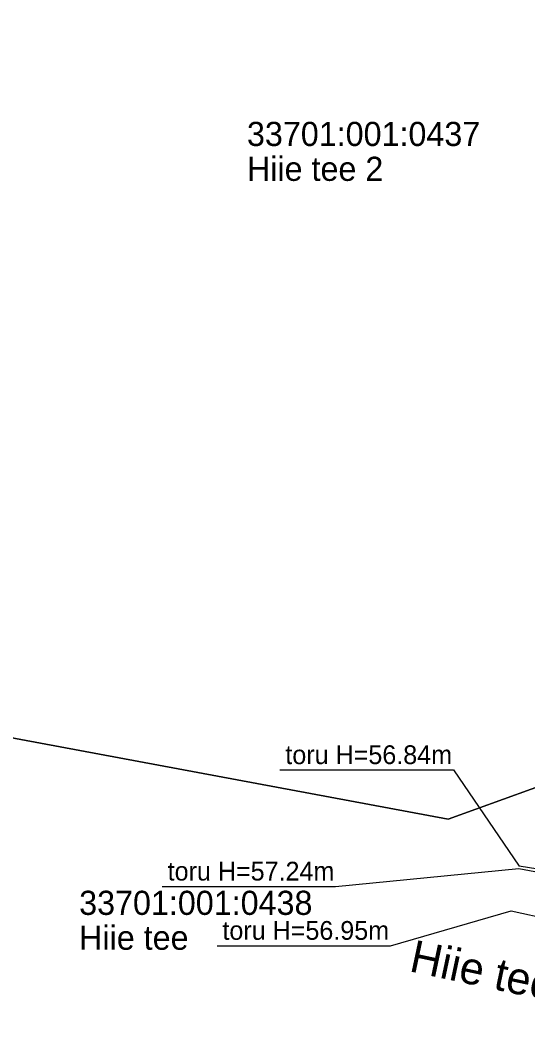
# Model space of a CAD drawing. Extents: x 551623 to 559850, y 6561220 to 6567135.
# Drawn here: x 556518.56 to 556537.49, y 6562459.97 to 6562497.86 of the extents above; entities that cross this region are included whole.
import ezdxf

# ---------------------------------------------------------------- set-up
doc = ezdxf.new("R2010")
doc.units = 0
for name, color, linetype in [('KTRASS', 7, 'Continuous'), ('PIIR', 7, 'Continuous'), ('SKTRASS', 7, 'Continuous'), ('TEE', 7, 'Continuous'), ('VTRASS', 7, 'Continuous')]:
    doc.layers.add(name, color=color, linetype=linetype)

msp = doc.modelspace()

# ---------------------------------------------------------------- linework, layer by layer
at = {"layer": 'KTRASS'}
msp.add_line((556537.155, 6562466.239), (556553.794, 6562463.06), dxfattribs=at)
msp.add_lwpolyline([(556523.858, 6562465.572), (556530.325, 6562465.572), (556537.155, 6562466.239)], dxfattribs=at)
at = {"layer": 'PIIR'}
for points in [[(556552.64, 6562513.89), (556543.81, 6562471.43), (556534.52, 6562468.08), (556501.37, 6562474.26), (556511.16, 6562521.05)], [(556543.81, 6562471.43), (556539.62, 6562450.85), (556532.43, 6562456.27), (556502.85, 6562461.78), (556483.73, 6562465.34), (556475, 6562460.86), (556460.95, 6562463.75), (556451.37, 6562418.32), (556447.11, 6562419.19), (556458.34, 6562474.13), (556459.95, 6562481.66), (556501.37, 6562474.26), (556534.52, 6562468.08)]]:
    msp.add_lwpolyline(points, close=True, dxfattribs=at)
at = {"layer": 'SKTRASS'}
msp.add_line((556536.872, 6562464.661), (556553.466, 6562460.999), dxfattribs=at)
msp.add_lwpolyline([(556525.901, 6562463.361), (556532.368, 6562463.361), (556536.872, 6562464.661)], dxfattribs=at)
at = {"layer": 'VTRASS'}
for points in [[(556528.249, 6562469.912), (556534.716, 6562469.912), (556537.17, 6562466.323)], [(556555.035, 6562463.463), (556537.17, 6562466.323)]]:
    msp.add_lwpolyline(points, dxfattribs=at)

# ---------------------------------------------------------------- texts
at = {"layer": 'KTRASS'}
msp.add_text('toru H=57.24m', height=0.7, dxfattribs=at).set_placement((556524.059, 6562465.791))
at = {"layer": 'PIIR'}
for s, p in [('33701:001:0437', (556527.018, 6562493.175)), ('Hiie tee 2', (556527.018, 6562491.875)), ('33701:001:0438', (556520.759, 6562464.51)), ('Hiie tee', (556520.759, 6562463.21))]:
    msp.add_text(s, height=0.9, dxfattribs=at).set_placement(p)
at = {"layer": 'SKTRASS'}
msp.add_text('toru H=56.95m', height=0.7, dxfattribs=at).set_placement((556526.102, 6562463.581))
at = {"layer": 'TEE'}
msp.add_text('Hiie tee', height=1.2, rotation=348.0029, dxfattribs=at).set_placement((556533.032, 6562462.415))
at = {"layer": 'VTRASS'}
msp.add_text('toru H=56.84m', height=0.7, dxfattribs=at).set_placement((556528.45, 6562470.132))

doc.saveas('drawing.dxf')
